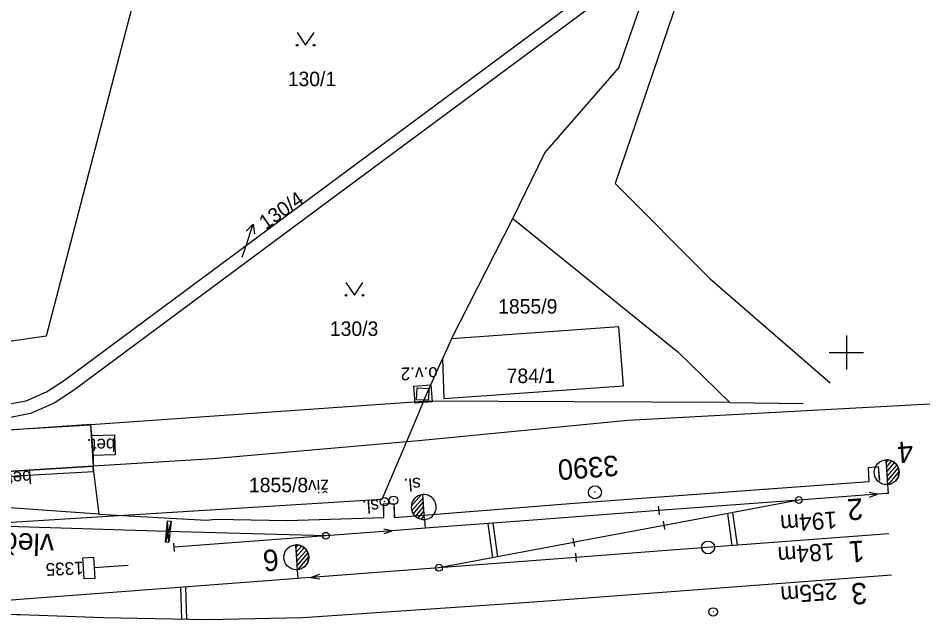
# Model space of a CAD drawing. Extents: x -779302 to -774398, y -1144902 to -1142831.
# Drawn here: x -774797.2 to -774690.2, y -1144431.5 to -1144360.8 of the extents above; entities that cross this region are included whole.
import ezdxf

# ---------------------------------------------------------------- set-up
doc = ezdxf.new("R2010")
doc.units = 0
for name, color, linetype in [('hektosit - Vrstva 5', 7, 'Continuous'), ('Hranice parcel', 7, 'Continuous'), ('Parcelní čísla', 7, 'Continuous'), ('Pop  PČ popisy', 7, 'Continuous'), ('Vnitřní kresba', 7, 'Continuous'), ('zjednodus_g_situ-seda - Vrstva 1', 7, 'Continuous'), ('zjednodus_g_situ-seda - Vrstva 12', 7, 'Continuous'), ('zjednodus_g_situ-seda - Vrstva 16', 7, 'Continuous'), ('zjednodus_g_situ-seda - Vrstva 2', 7, 'Continuous'), ('zjednodus_g_situ-seda - Vrstva 23', 7, 'Continuous'), ('zjednodus_g_situ-seda - Vrstva 25', 7, 'Continuous'), ('zjednodus_g_situ-seda - Vrstva 50', 7, 'Continuous'), ('zjednodus_g_situ-seda - Vrstva 63', 7, 'Continuous'), ('zjednodus_g_situ-seda - Vrstva 7', 7, 'Continuous'), ('zjednodus_g_situ-seda - Vrstva 8', 7, 'Continuous'), ('Značky kultur', 7, 'Continuous')]:
    doc.layers.add(name, color=color, linetype=linetype)

msp = doc.modelspace()

# ---------------------------------------------------------------- linework, layer by layer
at = {"layer": 'hektosit - Vrstva 5'}
for p, q in [((-774700, -1144398), (-774700, -1144402)), ((-774702, -1144400), (-774698, -1144400))]:
    msp.add_line(p, q, dxfattribs=at)
at = {"layer": 'Hranice parcel'}
for p, q in [((-774746.37, -1144398.39), (-774739.17, -1144384.29)), ((-774746.37, -1144398.39), (-774747.42, -1144400.74)), ((-774749.65, -1144405.72), (-774747.42, -1144400.74)), ((-774788.71, -1144408.47), (-774749.65, -1144405.72)), ((-774713.68, -1144405.89), (-774705.08, -1144406))]:
    msp.add_line(p, q, dxfattribs=at)
for points in [[(-774801.98, -1144406.47), (-774799.57, -1144406.26), (-774796.3, -1144405.69), (-774793.89, -1144404.6), (-774791.79, -1144403.24), (-774759.55, -1144379.36), (-774721.28, -1144350.96)], [(-774804.69, -1144399.57), (-774793.9, -1144398.06), (-774782, -1144352.41)], [(-774722.22, -1144353.64), (-774758.58, -1144380.6), (-774790.75, -1144404.47), (-774793.02, -1144405.95), (-774795.8, -1144407.18), (-774799.56, -1144407.9), (-774820.31, -1144409.63), (-774822.18, -1144410.3), (-774823.4, -1144411.16), (-774824.38, -1144412.31), (-774825.86, -1144415.63)], [(-774739.17, -1144384.29), (-774735.41, -1144376.57), (-774726.72, -1144366.58), (-774722.22, -1144353.64)], [(-774739.17, -1144384.29), (-774719.77, -1144399.93), (-774713.68, -1144405.89)], [(-774747.42, -1144400.74), (-774747.27, -1144405.4), (-774726.15, -1144403.92), (-774726.72, -1144397.01), (-774746.37, -1144398.39)], [(-774749.65, -1144405.72), (-774750.72, -1144408.24), (-774751.62, -1144410.36), (-774752.94, -1144413.48), (-774754.55, -1144417.27), (-774825.82, -1144421.69), (-774826.54, -1144421.73)], [(-774713.68, -1144405.89), (-774732.03, -1144405.8), (-774749.65, -1144405.72)], [(-774788.71, -1144408.47), (-774795.44, -1144408.94), (-774812.25, -1144410.04)], [(-774812.25, -1144410.04), (-774811.97, -1144414.8), (-774788.39, -1144413.36), (-774788.71, -1144408.47)]]:
    msp.add_lwpolyline(points, dxfattribs=at)
at = {"layer": 'Pop  PČ popisy'}
for p, q in [((-774770.59, -1144387.81), (-774769.66, -1144384.96)), ((-774769.66, -1144384.96), (-774770.45, -1144385.75)), ((-774769.66, -1144384.96), (-774769.5, -1144386.06)), ((-774770.92, -1144388.83), (-774770.59, -1144387.81))]:
    msp.add_line(p, q, dxfattribs=at)
at = {"layer": 'Vnitřní kresba'}
for p, q in [((-774717.01, -1144350.41), (-774727.14, -1144380.18)), ((-774727.14, -1144380.18), (-774715.99, -1144391.37)), ((-774715.99, -1144391.37), (-774701.89, -1144403.58))]:
    msp.add_line(p, q, dxfattribs=at)
at = {"layer": 'zjednodus_g_situ-seda - Vrstva 1'}
for points in [[(-774695.09, -1144416.54), (-774695.33, -1144416.56), (-774696.34, -1144416.63), (-774705.58, -1144417.32), (-774721.39, -1144420.3), (-774731.5, -1144422.2), (-774731.98, -1144422.29), (-774747.83, -1144425.26), (-774762.82, -1144426.39), (-774764.03, -1144426.49), (-774764.4, -1144426.51)], [(-774695.09, -1144416.54), (-774695.33, -1144416.56), (-774696.34, -1144416.63), (-774705.58, -1144417.32), (-774722, -1144418.55), (-774737.29, -1144419.71), (-774749.44, -1144420.63)], [(-774779.78, -1144421), (-774804.73, -1144420.22), (-774818.9, -1144419.64), (-774827.35, -1144419), (-774829.24, -1144418.79)], [(-774749.44, -1144420.63), (-774753.32, -1144420.92), (-774761.11, -1144421.51), (-774779.78, -1144421)], [(-774749.44, -1144420.63), (-774753.32, -1144420.92), (-774761.11, -1144421.51), (-774778.91, -1144422.85)], [(-774695.01, -1144421.28), (-774721.06, -1144423.24), (-774731.26, -1144424.01), (-774731.71, -1144424.05), (-774747.83, -1144425.26), (-774762.82, -1144426.39), (-774764.03, -1144426.49), (-774764.4, -1144426.51)], [(-774694.69, -1144426.13), (-774721.06, -1144428.11), (-774736.69, -1144429.29), (-774763.81, -1144431.14), (-774775.1, -1144431.37), (-774787.23, -1144431.13), (-774796.99, -1144430.79), (-774797.44, -1144430.78), (-774813.59, -1144430.23), (-774828.58, -1144431.36), (-774829.12, -1144431.4), (-774830.16, -1144431.48)], [(-774764.4, -1144426.51), (-774781.47, -1144427.81), (-774797.03, -1144428.98), (-774797.52, -1144429.01), (-774813.59, -1144430.23), (-774828.58, -1144431.36), (-774829.12, -1144431.4), (-774830.16, -1144431.48)]]:
    msp.add_lwpolyline(points, dxfattribs=at)
at = {"layer": 'zjednodus_g_situ-seda - Vrstva 12'}
msp.add_lwpolyline([(-774750.45, -1144405.56), (-774750.38, -1144404.15), (-774749.01, -1144404.23), (-774749.05, -1144405.6), (-774750.45, -1144405.56)], dxfattribs=at)
at = {"layer": 'zjednodus_g_situ-seda - Vrstva 16'}
for p, q in [((-774697.41, -1144413.51), (-774697.42, -1144413.51)), ((-774696.26, -1144413.39), (-774696.26, -1144413.39)), ((-774697.31, -1144415.13), (-774697.31, -1144415.13)), ((-774696.16, -1144415), (-774696.1, -1144415)), ((-774754.31, -1144417.78), (-774754.34, -1144417.78)), ((-774753.13, -1144417.74), (-774753.14, -1144417.74)), ((-774754.3, -1144419.37), (-774754.29, -1144419.37)), ((-774753.07, -1144419.35), (-774753.08, -1144419.35))]:
    msp.add_line(p, q, dxfattribs=at)
for points in [[(-774690.21, -1144406.05), (-774725.66, -1144407.99), (-774749.81, -1144410.32), (-774774.4, -1144412.48), (-774788.44, -1144413.35)], [(-774788.62, -1144409.75), (-774785.94, -1144409.67), (-774785.83, -1144412.02), (-774788.44, -1144412.08), (-774788.62, -1144409.75)], [(-774804.7, -1144414.35), (-774804.67, -1144414.85), (-774788.38, -1144413.97), (-774788.44, -1144413.35), (-774804.7, -1144414.35)], [(-774788.44, -1144413.35), (-774788.38, -1144413.97), (-774787.77, -1144418.98), (-774775.13, -1144419.68), (-774774.08, -1144419.56), (-774765.67, -1144419.72), (-774754.3, -1144419.37), (-774754.31, -1144417.78), (-774753.13, -1144417.74), (-774753.07, -1144419.35), (-774731.96, -1144417.67), (-774710.73, -1144416.13), (-774697.31, -1144415.13), (-774697.41, -1144413.51), (-774696.26, -1144413.39), (-774696.16, -1144415)], [(-774775.13, -1144419.68), (-774774.08, -1144419.56), (-774765.68, -1144419.72), (-774754.29, -1144419.37), (-774754.34, -1144417.78), (-774753.14, -1144417.74), (-774753.08, -1144419.35), (-774731.94, -1144417.68), (-774710.72, -1144416.12), (-774697.31, -1144415.13), (-774697.42, -1144413.51), (-774696.26, -1144413.39), (-774696.1, -1144415)], [(-774812, -1144414.79), (-774804.7, -1144414.35), (-774804.67, -1144414.85), (-774788.38, -1144413.97), (-774787.77, -1144418.98), (-774802.14, -1144417.95), (-774811.88, -1144418.11), (-774826.73, -1144417.54), (-774825.79, -1144415.35), (-774812, -1144414.79)]]:
    msp.add_lwpolyline(points, dxfattribs=at)
at = {"layer": 'zjednodus_g_situ-seda - Vrstva 2'}
for p, q in [((-774695.38, -1144412.59), (-774695.16, -1144415.51)), ((-774695.36, -1144412.97), (-774695.05, -1144412.61)), ((-774695.32, -1144413.5), (-774694.65, -1144412.73)), ((-774695.28, -1144414.03), (-774694.34, -1144412.93)), ((-774695.24, -1144414.56), (-774694.08, -1144413.21)), ((-774695.2, -1144415.09), (-774693.9, -1144413.57)), ((-774695.06, -1144415.49), (-774693.82, -1144414.06)), ((-774695.16, -1144415.51), (-774695.09, -1144416.54)), ((-774751.08, -1144418.05), (-774749.93, -1144416.71)), ((-774751.02, -1144418.56), (-774749.7, -1144417.04)), ((-774749.51, -1144419.6), (-774749.73, -1144416.68)), ((-774750.84, -1144418.94), (-774749.67, -1144417.57)), ((-774750.59, -1144419.23), (-774749.63, -1144418.11)), ((-774721.94, -1144419.05), (-774722.05, -1144418.05)), ((-774705.58, -1144417.32), (-774721.39, -1144420.3)), ((-774750.28, -1144419.45), (-774749.59, -1144418.64)), ((-774749.89, -1144419.58), (-774749.55, -1144419.18)), ((-774749.51, -1144419.6), (-774749.44, -1144420.63)), ((-774721.3, -1144420.79), (-774721.48, -1144419.81)), ((-774779.79, -1144421.49), (-774779.76, -1144420.5)), ((-774761.11, -1144421.51), (-774779.78, -1144421)), ((-774778.88, -1144423.35), (-774778.95, -1144422.36)), ((-774731.98, -1144422.29), (-774747.83, -1144425.26)), ((-774731.89, -1144422.78), (-774732.08, -1144421.8)), ((-774764.69, -1144422.57), (-774764.47, -1144425.49)), ((-774764.67, -1144422.95), (-774764.36, -1144422.58)), ((-774764.63, -1144423.48), (-774763.96, -1144422.71)), ((-774764.59, -1144424), (-774763.65, -1144422.91)), ((-774764.55, -1144424.53), (-774763.39, -1144423.19)), ((-774764.51, -1144425.06), (-774763.21, -1144423.55)), ((-774764.36, -1144425.47), (-774763.13, -1144424.03)), ((-774731.67, -1144424.55), (-774731.75, -1144423.55)), ((-774764.47, -1144425.49), (-774764.4, -1144426.51))]:
    msp.add_line(p, q, dxfattribs=at)
for points in [[(-774695.09, -1144416.54), (-774695.33, -1144416.56), (-774696.34, -1144416.63), (-774705.58, -1144417.32), (-774722, -1144418.55)], [(-774697.28, -1144416.96), (-774696.34, -1144416.63), (-774697.32, -1144416.44)], [(-774749.44, -1144420.63), (-774753.32, -1144420.92), (-774761.11, -1144421.51), (-774778.91, -1144422.85)], [(-774754.26, -1144421.25), (-774753.32, -1144420.92), (-774754.3, -1144420.74)], [(-774731.71, -1144424.05), (-774747.83, -1144425.26), (-774762.82, -1144426.39), (-774764.03, -1144426.49), (-774764.4, -1144426.51)], [(-774761.87, -1144426.06), (-774762.82, -1144426.39), (-774761.83, -1144426.58)]]:
    msp.add_lwpolyline(points, dxfattribs=at)
for centre, radius in [((-774695.27, -1144414.05), 1.46), ((-774705.58, -1144417.32), 0.4), ((-774761.11, -1144421.51), 0.4), ((-774764.58, -1144424.03), 1.46), ((-774747.83, -1144425.26), 0.4)]:
    msp.add_circle(centre, radius, dxfattribs=at)
for centre, start, end in [((-774695.27, -1144414.05), 274.3012, 94.262), ((-774749.62, -1144418.14), 94.2772, 274.238), ((-774749.61, -1144418.14), 274.0228, 94.4924), ((-774764.58, -1144424.03), 274.3266, 94.2875)]:
    msp.add_arc(centre, 1.46, start, end, dxfattribs=at)
at = {"layer": 'zjednodus_g_situ-seda - Vrstva 23'}
msp.add_lwpolyline([(-774812, -1144414.79), (-774812.4, -1144409.88), (-774788.73, -1144408.51), (-774788.62, -1144409.75), (-774788.44, -1144412.08), (-774788.44, -1144413.35), (-774804.7, -1144414.35), (-774812, -1144414.79)], dxfattribs=at)
at = {"layer": 'zjednodus_g_situ-seda - Vrstva 25'}
msp.add_lwpolyline([(-774750.78, -1144403.96), (-774748.78, -1144403.81), (-774748.63, -1144405.8), (-774750.62, -1144405.96)], close=True, dxfattribs=at)
at = {"layer": 'zjednodus_g_situ-seda - Vrstva 50'}
for p, q in [((-774754.19, -1144417.5), (-774754.29, -1144417.51)), ((-774753.12, -1144417.34), (-774753.22, -1144417.35))]:
    msp.add_line(p, q, dxfattribs=at)
for centre in [(-774754.24, -1144417.51), (-774753.17, -1144417.35)]:
    msp.add_circle(centre, 0.5, dxfattribs=at)
at = {"layer": 'zjednodus_g_situ-seda - Vrstva 63'}
msp.add_line((-774729.47, -1144416.4), (-774729.57, -1144416.41), dxfattribs=at)
msp.add_circle((-774729.52, -1144416.4), 0.756, dxfattribs=at)
at = {"layer": 'zjednodus_g_situ-seda - Vrstva 7'}
for p, q in [((-774713.4, -1144422.66), (-774713.9, -1144418.89)), ((-774712.8, -1144422.62), (-774713.31, -1144418.78)), ((-774779.29, -1144419.81), (-774779.94, -1144422.26)), ((-774741.52, -1144424.08), (-774742.05, -1144420.07)), ((-774740.93, -1144423.97), (-774741.45, -1144420.02)), ((-774713.36, -1144420.69), (-774713.36, -1144420.69)), ((-774741.51, -1144421.91), (-774741.51, -1144421.91)), ((-774778.03, -1144431.31), (-774778.14, -1144427.55)), ((-774777.43, -1144431.32), (-774777.54, -1144427.51)), ((-774777.79, -1144429.45), (-774777.79, -1144429.45)), ((-774715.59, -1144430.45), (-774715.69, -1144430.46))]:
    msp.add_line(p, q, dxfattribs=at)
msp.add_lwpolyline([(-774779.54, -1144422.3), (-774779.69, -1144419.77), (-774779.29, -1144419.81), (-774779.54, -1144422.3), (-774779.94, -1144422.26), (-774779.69, -1144419.77)], dxfattribs=at)
for centre, radius in [((-774716.23, -1144422.88), 0.75), ((-774715.64, -1144430.45), 0.5)]:
    msp.add_circle(centre, radius, dxfattribs=at)
at = {"layer": 'zjednodus_g_situ-seda - Vrstva 8'}
msp.add_line((-774784.32, -1144425.01), (-774788.31, -1144425.26), dxfattribs=at)
msp.add_lwpolyline([(-774788.39, -1144424.01), (-774788.23, -1144426.51), (-774789.48, -1144426.58), (-774789.64, -1144424.09)], close=True, dxfattribs=at)
at = {"layer": 'Značky kultur'}
for points in [[(-774764.49, -1144362.45), (-774763.49, -1144363.95), (-774762.49, -1144362.45)], [(-774758.75, -1144391.78), (-774757.75, -1144393.28), (-774756.75, -1144391.78)]]:
    msp.add_lwpolyline(points, dxfattribs=at)
for centre in [(-774764.49, -1144363.95), (-774762.49, -1144363.95), (-774758.75, -1144393.28), (-774756.75, -1144393.28)]:
    msp.add_circle(centre, 0.1, dxfattribs=at)

# ---------------------------------------------------------------- texts
at = {"layer": 'Parcelní čísla'}
for s, p in [('130/1', (-774765.59, -1144368.75)), ('1855/9', (-774740.88, -1144395.44)), ('130/3', (-774760.64, -1144398.06)), ('784/1', (-774739.89, -1144403.59)), ('1855/8', (-774770.14, -1144416.4))]:
    msp.add_text(s, height=1.7, dxfattribs=at).set_placement(p)
msp.add_text('130/4', height=1.7, rotation=35, dxfattribs=at).set_placement((-774768.19, -1144385.65))
at = {"layer": 'zjednodus_g_situ-seda - Vrstva 1'}
for s, height, rotation, p in [('2', 2.5, 184.281, (-774698.13, -1144417.09)), ('194m', 2, 184.281, (-774701.17, -1144418.63)), ('vlečka ZZN', 2.5, 178.212, (-774792.99, -1144421.32)), ('184m', 2, 184.3144, (-774701.47, -1144422.33)), ('1', 2.5, 184.3144, (-774697.94, -1144422.04)), ('255m', 2, 184.3038, (-774701.14, -1144426.98)), ('3', 2.5, 184.3038, (-774697.66, -1144426.98))]:
    msp.add_text(s, height=height, rotation=rotation, dxfattribs=at).set_placement(p)
at = {"layer": 'zjednodus_g_situ-seda - Vrstva 16'}
for s, rotation, p in [('bet.', 181.101, (-774785.83, -1144410.09)), ('bet.', 184.7062, (-774795.7, -1144413.84)), ('živ.', 181.7385, (-774760.78, -1144414.92))]:
    msp.add_text(s, height=1.5, rotation=rotation, dxfattribs=at).set_placement(p)
at = {"layer": 'zjednodus_g_situ-seda - Vrstva 2'}
for s, rotation, p in [('4', 184.2821, (-774692.23, -1144410.39)), ('6', 184.3075, (-774766.73, -1144423.07))]:
    msp.add_text(s, height=2.5, rotation=rotation, dxfattribs=at).set_placement(p)
at = {"layer": 'zjednodus_g_situ-seda - Vrstva 25'}
msp.add_text('o.v.2', height=1.5, rotation=180.4793, dxfattribs=at).set_placement((-774747.98, -1144401.73))
at = {"layer": 'zjednodus_g_situ-seda - Vrstva 50'}
for rotation, p in [(184.2576, (-774750.01, -1144414.68)), (184.3346, (-774754.91, -1144417.24))]:
    msp.add_text('sl.', height=1.5, rotation=rotation, dxfattribs=at).set_placement(p)
at = {"layer": 'zjednodus_g_situ-seda - Vrstva 63'}
msp.add_text('3390', height=2.4, rotation=184.3245, dxfattribs=at).set_placement((-774726.84, -1144412.06))
at = {"layer": 'zjednodus_g_situ-seda - Vrstva 8'}
msp.add_text('1335', height=1.5, rotation=182.5652, dxfattribs=at).set_placement((-774789.58, -1144424.53))

doc.saveas('drawing.dxf')
